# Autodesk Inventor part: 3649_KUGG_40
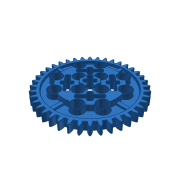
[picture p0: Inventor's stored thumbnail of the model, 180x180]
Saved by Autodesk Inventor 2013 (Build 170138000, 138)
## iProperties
Created: 2013-03
Part Number: 3649_KUGG_40
Material: Steel, Galvanized
Document SubType Name: Modeling
Designer: perblt
Density: 1 g/cm^3
Translation Standard: STEP AP203
FileName: 3649_KUGG_40
PreProcessor: PRO/ENGINEER BY PARAMETRIC TECHNOLOGY CORPORATION, 2010370
PostProcessor: Build: 138, Release: 2013 RTM - Date: Thu 03/01/2012
Sent Units: millimeter
Uncertainty: 0.005965069985406
Author: perblt
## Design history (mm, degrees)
node "3649_KUGG_401"
fillet "Fillet1" dims "d0" = 0.1, "d1" = 0.1
node "3649_KUGG_40"
node "Base1"
